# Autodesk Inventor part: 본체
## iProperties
Created: 2014-11
Part Number: 본체
Material: 알루미늄-6061
Document SubType Name: Modeling
Designer: elite
Mass: 2852.49 g
Surface Area: 2106.73 cm^2
Volume: 1052.58 cm^3
Density: 2.71 g/cm^3
Author: elite
